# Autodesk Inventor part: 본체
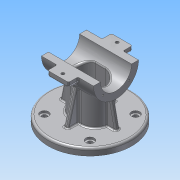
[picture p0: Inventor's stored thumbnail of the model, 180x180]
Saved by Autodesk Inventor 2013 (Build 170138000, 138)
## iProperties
Created: 2015-12
Part Number: 본체
Material: 알루미늄 6061
Document SubType Name: Modeling
Designer: mduedu
Density: 2.71 g/cm^3
Mass: 580.908 g
Surface Area: 555.6 cm^2
Volume: 214.357 cm^3
Author: mduedu
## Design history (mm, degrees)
sketch "스케치1"
  geometry: L1 (45, 40)-(-45, 40); L2 (-45, 40)-(-45, -40); L3 (-45, -40)-(45, -40); L4 (45, -40)-(45, 40); L5 (45, 40)-(-45, -40); L6 (-45, 40)-(45, -40); 2 further points
  constraints: 12 end point, 2 midpoint, 2 parallel, 1 coincident, 1 horizontal, 1 perpendicular, 3 other
  dimensions: "d0" = 90 distance of L2.end L3.end; "d2" = 80 distance of L1.end L2.end
extrude "돌출1" new body sketch "스케치1" distance "d3" = 10; taper "d4" = 0 deg
sketch "스케치2"
  geometry: C1 r 32.5 at (80, 0); 1 further point
  constraints: 1 centre point
  dimensions: "d5" = 65 diameter of C1; "d116" = 80 distance of point (0, 0) C1.centre
extrude "돌출2" join sketch "스케치2" stored distance "d7" = 75; taper "d8" = 0 deg
sketch "스케치3"
  geometry: L1 (-27.5, -20)-(27.5, -20); L2 (27.5, -20)-(27.5, 20); L3 (27.5, 20)-(-27.5, 20); L4 (-27.5, 20)-(-27.5, -20); L5 (-27.5, -20)-(27.5, 20); L6 (27.5, -20)-(-27.5, 20); 1 further point
  constraints: 12 end point, 2 midpoint, 2 parallel, 1 horizontal, 1 perpendicular
  dimensions: "d9" = 55 distance of L2.end L3.end; "d11" = 40 distance of L1.end L2.end
extrude "돌출3" new body sketch "스케치3" stored distance "d12" = 75; taper "d13" = 0 deg
fillet "모깎기1"
fillet "모깎기2"
feature "결합1"
  node "솔리드2"
sketch "스케치4"
  geometry: L1 (-37.5, 47.5)-(37.5, 47.5) reference; L2 (32.5, 47.5)-(40.208, 10); L3 (37.5, 47.5)-(37.5, 112.5) reference; L4 (60.208, 0)-(60.208, 10) reference; L5 (60.208, 10)-(-60.208, 10) reference; 1 further point
  constraints: 2 end point, 2 point on line
  dimensions: "d15" = 5 distance from line of L2.start L3; "d117" = 20 distance from line of L2.end L4
sketch "스케치5"
  geometry: L1 (10, 35.208)-(56.729, 22.687); L2 (0, 60.208)-(10, 60.208) reference; L3 (10, -60.208)-(10, 60.208) reference; 2 further points
  constraints: 2 end point, 1 point on line, 2 other
  dimensions: "d118" = 25 distance from line of L1.start L2; "d119" = 75 deg angle of L1 L3
feature "리브1" dims "d19" = 1, "d20" = 6, "d21" = 0, "d22" = 0, "d23" = 1, "d24" = 1
feature "리브2" dims "d25" = 1, "d26" = 6, "d27" = 0, "d28" = 0, "d29" = 1, "d30" = 1
fillet "모깎기4" dims "d31" = 2
fillet "모깎기5" dims "d32" = 2
fillet "모깎기6" dims "d33" = 2
sketch "스케치6"
  geometry: L1 (0, 0)-(-32.88, 32.88); L2 (0, 0)-(-46.5, 0); A1 r 46.5 centre (0, 0) between (-32.88, 32.88) and (-46.5, 0); 5 further points
  constraints: 4 end point, 2 coincident, 2 point on circle, 1 centre point, 1 horizontal, 5 other
  dimensions: "d120" = 93 diameter of A1; "d122" = 45 deg angle of L1 L2; "d126" = 360 deg dimension on point (0, 0) point (-32.88, 32.88) (derived)
hole "구멍1" sketch "스케치6" at (-32.88, 32.88), (-32.88, -32.88), (32.88, -32.88), (32.88, 32.88) diameter "d34" = 7; stored, may be unused: countersink angle "d38" = 90 deg, drill point angle "d40" = 118 deg; dims "d35" = 6, "d36" = 12, "d37" = 3, "d39" = 8
fillet "모깎기13" dims "d131" = 3
hole "구멍2" diameter "d44" = 45; stored, may be unused: countersink angle "d48" = 90 deg, drill point angle "d50" = 118 deg; dims "d42" = 10, "d43" = 10, "d45" = 6, "d46" = 4, "d47" = 2, "d49" = 8
sketch "스케치7" dims "d52" = 26.5
  geometry: L1 (0, 0)-(32.5, 0); L2 (0, 0)-(22.981, 22.981); A1 r 32.5 centre (0, 0) between (32.5, 0) and (22.981, 22.981) reference; 3 further points
  constraints: 4 end point, 2 point on circle, 1 coincident, 1 horizontal, 1 point on line, 3 other
  dimensions: "d51" = 45 deg angle of L2 L1
hole "구멍3" sketch "스케치7" at (18.738, 18.738) diameter "d54" = 2.459; stored, may be unused: countersink angle "d58" = 90 deg, drill point angle "d60" = 118 deg; dims "d55" = 8, "d56" = 4, "d57" = 2, "d59" = 10
sketch "스케치8"
  geometry: L1 (72.5, 31.623)-(72.5, 46); L2 (72.5, 46)-(87.5, 46); L3 (87.5, 46)-(87.5, 31.623); A1 r 32.5 centre (80, 0) between (87.5, 31.623) and (72.5, 31.623) reference; 2 further points
  constraints: 6 end point, 2 point on circle, 1 horizontal, 1 midpoint, 1 parallel, 1 vertical, 1 vertical alignment
  dimensions: "d64" = 15 distance of L1.end L2.end; "d66" = 46 distance from line of L2 A1.centre
extrude "돌출4" join sketch "스케치8" stored distance "d67" = 30; taper "d68" = 0 deg
fillet "모깎기8" dims "d69" = 3
fillet "모깎기9" dims "d70" = 2
node "작업 평면2"
sketch "스케치16"
  geometry: L1 (33.166, 72.5)-(44, 72.5) reference; L2 (42.5, 72.5)-(28.53, 64.434); L3 (46, 75.5)-(46, 84.5) reference; 2 further points
  constraints: 2 end point, 1 point on line, 2 other
  dimensions: "d138" = 30 deg angle of L2 L1; "d139" = 3.5 distance from line of L2.start L3
feature "리브3" sketch "스케치16" dims "d140" = 1, "d141" = 3, "d142" = 0, "d143" = 0, "d144" = 1, "d145" = 1
fillet "모깎기14" dims "d146" = 1
fillet "모깎기15" dims "d147" = 1
sketch "스케치9"
  geometry: L1 (-76, 82.5)-(76, 82.5); L2 (76, 82.5)-(76, 0); L3 (76, 0)-(-76, 0); L4 (-76, 0)-(-76, 82.5); L5 (-46, 4.5)-(-46, -4.5) reference; C1 r 32.5 at (0, 0) reference; 2 further points
  constraints: 8 end point, 2 parallel, 1 coincident, 1 horizontal, 1 midpoint, 1 perpendicular
  dimensions: "d71" = 50 distance edge to line of C1 L1; "d72" = 30 distance between parallel lines of L4 L5
extrude "돌출5" cut sketch "스케치9" stored distance "d73" = 0; taper "d74" = 0 deg
node "작업 평면1"
sketch "스케치10"
  geometry: L1 (-7.5, 15)-(7.5, 15); L2 (-7.5, -15)-(7.5, -15); A1 r 20 centre (-7.5, 0) between (-7.5, 20) and (-26.977, 4.545) reference; A2 r 20 centre (7.5, 0) between (26.977, 4.545) and (7.5, 20) reference; A3 r 15 centre (-7.5, 0) between (-7.5, 15) and (-7.5, -15); A4 r 15 centre (7.5, 0) between (7.5, -15) and (7.5, 15); 1 further point
  constraints: 7 point on circle, 4 end point, 4 tangent, 3 point on line, 2 centre point, 2 coincident, 1 horizontal
  dimensions: "d77" = 5 radial gap between concentric circles of A3 A1
extrude "돌출6" cut sketch "스케치10" stored distance "d78" = 50; taper "d79" = 0 deg
fillet "모깎기10" dims "d80" = 3
sketch "스케치11"
  geometry: 2 further points
  constraints: 1 coincident
hole "구멍4" sketch "스케치11" at (0, 0) diameter "d81" = 12; stored, may be unused: countersink angle "d85" = 90 deg, drill point angle "d87" = 118 deg; dims "d82" = 8, "d83" = 40, "d84" = 10, "d86" = 10
sketch "스케치12"
  geometry: C1 r 10 at (0, 0); 1 further point
  constraints: 1 centre point, 1 coincident
  dimensions: "d88" = 20 diameter of C1
extrude "돌출7" cut sketch "스케치12" distance "d89" = 5; taper "d90" = 0 deg
chamfer "모따기1" distance "d91" = 1; stored, may be unused: second distance "d92" = 2, angle "d93" = 45 deg
fillet "모깎기11" dims "d94" = 0.5
sketch "스케치13"
  geometry: L1 (-3, 10.834)-(-3, 1.039) reference; L2 (27, 1.039)-(27, 10.834) reference; L3 (-3, 5.936)-(27, 5.936); L4 (24, 12.834)-(0, 12.834) reference; L5 (12, 12.834)-(12, -33.166); 1 further point
  constraints: 4 end point, 4 midpoint, 1 perpendicular, 1 point on line
hole "구멍5" sketch "스케치13" at (12, 5.936) diameter "d101" = 4.5; stored, may be unused: countersink angle "d105" = 90 deg, drill point angle "d107" = 0 deg; dims "d102" = 6, "d103" = 4, "d104" = 2, "d106" = 8
fillet "모깎기12" dims "d115" = 0.3
node "솔리드1"
mirror "대칭1"
mirror "대칭2"
pattern_circular "원형 패턴1" dims angle "d62" = 360 deg
mirror "대칭3"
mirror "대칭7"
mirror "대칭4"
mirror "대칭6"
other parameters: "d137" = -5
